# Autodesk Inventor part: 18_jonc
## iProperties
Shininess: 20.0
Length Units: 11270
Angle Units: 11279
Time Units: 11290
Mass Units: 11283
Length Display Precision: 3
Angle Display Precision: 2
Created: 2000-10
Part Number: 18_jonc
Material: Par défaut
Document SubType Name: Modélisation
Density: 0.0
Volumn: 0.0
Area: 0.0
PropertySet Name: Model Information
Control State: 0
Master: False
Checked Out: False
Author: Laurent GAUTHERON
